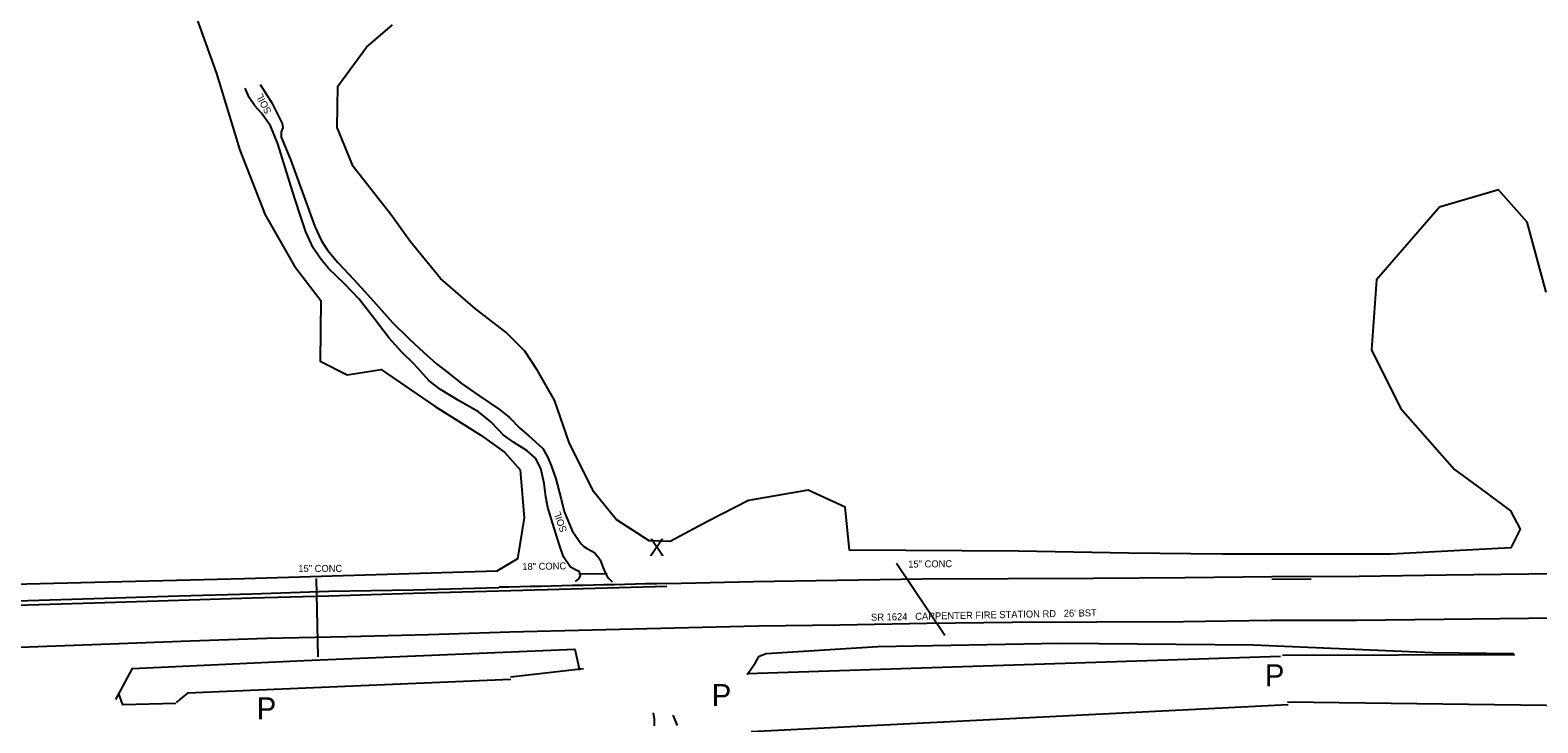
# Model space of a CAD drawing. Extents: x 2030130 to 2036320, y 723205 to 762423.
# Drawn here: x 2031448 to 2032310, y 754334 to 754729 of the extents above; entities that cross this region are included whole.
import ezdxf

# ---------------------------------------------------------------- set-up
doc = ezdxf.new("R2010")
doc.units = 0
for name, color, linetype in [('Draft_Station Labels Major', 7, 'Continuous'), ('Draft_Station Tics Major', 7, 'Continuous'), ('Draft_Station Tics Minor', 7, 'Continuous'), ('Old_Level_23', 7, 'Continuous'), ('Old_Level_26', 7, 'Continuous'), ('Prop Horizontal Alignment Ramp', 7, 'Continuous')]:
    doc.layers.add(name, color=color, linetype=linetype)

msp = doc.modelspace()

# ---------------------------------------------------------------- linework, layer by layer
at = {"layer": 'Draft_Station Labels Major'}
for p, q in [((2031574.67, 754404.91), (2031618.56, 754406.17)), ((2031618.56, 754406.17), (2031666.97, 754407.55)), ((2031666.97, 754407.55), (2031715.65, 754408.99)), ((2031440.17, 754400.79), (2031484.32, 754402.17)), ((2031484.32, 754402.17), (2031532.82, 754403.6)), ((2031532.82, 754403.6), (2031574.67, 754404.91))]:
    msp.add_line(p, q, dxfattribs=at)
for points in [[(2031759.54, 754414.3), (2031761.49, 754415.85), (2031762.43, 754417.62), (2031762.32, 754418.95), (2031761.64, 754419.94), (2031760.26, 754420.54), (2031756.68, 754422.5), (2031752.82, 754428.45), (2031750.48, 754435.12), (2031746.61, 754447.29), (2031743.86, 754456.61), (2031742.66, 754462.58), (2031741.63, 754470.31), (2031739.79, 754478.89), (2031736.7, 754484.84), (2031731.86, 754489.02), (2031724.12, 754493.98), (2031718.29, 754498.1), (2031715.5, 754500.97), (2031711.14, 754505.49), (2031704.06, 754511.16), (2031693.07, 754517.47), (2031682.47, 754524.06), (2031675.82, 754528.98), (2031670.87, 754534.39), (2031667.22, 754538.68), (2031660.32, 754545.31), (2031653.07, 754553.35), (2031644.42, 754564.48), (2031635.81, 754575.6), (2031627.55, 754584.4), (2031618.35, 754593.14), (2031613.5, 754599.08), (2031609.64, 754605.02), (2031605.42, 754614.1), (2031601.75, 754624.89), (2031597.69, 754637.24), (2031589.31, 754664.37), (2031585.17, 754674.73), (2031580.07, 754681.8), (2031576.18, 754685.99), (2031573, 754690.85), (2031570.76, 754696.19)], [(2031579.34, 754698.22), (2031585.94, 754687.84), (2031591.85, 754675.93), (2031592.16, 754673.51), (2031591.33, 754671.23), (2031591.26, 754668.23), (2031596.61, 754655.42), (2031604.96, 754632.37), (2031610.43, 754617.14), (2031614.3, 754608.87), (2031617.82, 754603.58), (2031623.64, 754596.56), (2031630.11, 754589.69), (2031636.98, 754582.31), (2031645.76, 754572.51), (2031654.93, 754562.3), (2031664.47, 754552.94), (2031672.62, 754545.38), (2031680.09, 754538.61), (2031686.55, 754533.64), (2031694.35, 754527.45), (2031704.39, 754520.66), (2031716.15, 754512.66), (2031721.8, 754507.97), (2031727.79, 754501.85), (2031732.82, 754497.58), (2031736.46, 754494.34), (2031740.87, 754490.2), (2031743.62, 754485.48), (2031745.71, 754480.56), (2031748.3, 754473.04), (2031751.41, 754461.25), (2031753.19, 754454.28), (2031757.62, 754443.26), (2031762.77, 754435.81), (2031764.35, 754434.31), (2031765.79, 754433.37), (2031767.65, 754432.39), (2031768.89, 754431.69), (2031770.85, 754430.24), (2031772, 754429.02), (2031773.01, 754427.84), (2031773.64, 754426.66), (2031775.49, 754422.07), (2031776.27, 754419.89), (2031776.85, 754418.62), (2031777.72, 754417.1), (2031778.63, 754415.97), (2031780.6, 754414.09)], [(2031811.89, 754413.13), (2031861.33, 754414.38), (2031909.16, 754415.12), (2031958.06, 754415.73), (2032007.08, 754416.04), (2032055.76, 754416.25), (2032108.13, 754416.62), (2032157.75, 754417.06), (2032207.7, 754417.33), (2032257.5, 754418.05), (2032304.72, 754418.6), (2032351.94, 754419.11), (2032398.25, 754419.75), (2032449.52, 754420.76), (2032467.91, 754421.36), (2032499.63, 754422.6), (2032537.02, 754423.46)], [(2032157.76, 754415.61), (2032180.27, 754415.79)], [(2031026.74, 754387.19), (2031087.38, 754389.72), (2031140.32, 754391.43), (2031191.98, 754393.68), (2031244.3, 754395.39), (2031296.79, 754397.49), (2031347.82, 754399.72), (2031392.09, 754401.58), (2031440.04, 754403.3), (2031484.2, 754404.5), (2031532.77, 754406.1), (2031574.56, 754407.31), (2031618.48, 754408.73), (2031666.93, 754409.56), (2031715.67, 754410.95)], [(2031715.65, 754408.99), (2031764.02, 754410.28), (2031811.79, 754411.53)], [(2031401.23, 754375.11), (2031446.88, 754377.01), (2031493.42, 754378.62), (2031539.16, 754380.32), (2031583.12, 754381.86), (2031629.01, 754382.93), (2031675.51, 754383.95), (2031722, 754385.62), (2031769.03, 754386.67), (2031816.14, 754387.79), (2031864.12, 754389), (2031910.83, 754389.54), (2031960.57, 754390.48), (2032009.47, 754390.99), (2032057.5, 754391.22), (2032107.26, 754391.52), (2032157.41, 754392.21), (2032206.33, 754392.27)], [(2032206.33, 754392.27), (2032256.13, 754392.71), (2032304.69, 754393.4), (2032351.64, 754393.89)], [(2031804.83, 754331.89), (2031804.79, 754335.59), (2031804.28, 754339.19)], [(2031815.3, 754337.97), (2031817.74, 754331.92)]]:
    msp.add_lwpolyline(points, dxfattribs=at)
msp.add_arc((2040522.98, 366896.92), 387614.11, 91.2877516, 91.3019787, dxfattribs=at)
at = {"layer": 'Draft_Station Tics Major'}
for p, q in [((2032162.74, 754371.48), (2031857.84, 754361.58)), ((2032296.83, 754372.45), (2032163.84, 754371.96)), ((2031764.07, 754364.44), (2031722.38, 754359.66)), ((2032166.83, 754345.57), (2032331.51, 754343.51)), ((2031860.04, 754328.57), (2032167.14, 754343.97))]:
    msp.add_line(p, q, dxfattribs=at)
for points in [[(2031533.5, 754762.53), (2031554.26, 754704.61), (2031567.65, 754660.73), (2031582.11, 754623.71), (2031598.79, 754594.53), (2031614.03, 754574.86), (2031613.61, 754540.18), (2031628.93, 754532.32), (2031648.53, 754535.37), (2031679.41, 754514.33), (2031705.49, 754497.82), (2031718.92, 754488.23), (2031727.97, 754478.03), (2031730.15, 754450.61), (2031726.37, 754427.33), (2031714.63, 754420.16), (2031570.23, 754415.89), (2031383.35, 754411.21)], [(2032314.64, 754579.61), (2032303.77, 754619.52), (2032287.39, 754638.03), (2032253.76, 754628.18), (2032217.77, 754586.67), (2032214.73, 754546.62), (2032231.45, 754513.25), (2032262.28, 754478.3), (2032280.7, 754464.76), (2032294.33, 754454.6), (2032299.77, 754444.17), (2032294.54, 754433.45), (2032225.97, 754429.92), (2032129.36, 754429.93), (2032075.81, 754430.55), (2032012.92, 754431.65), (2031916.31, 754432.23), (2031913.78, 754456.79), (2031892.72, 754466.49), (2031858.48, 754460.63), (2031835.54, 754448.78), (2031813.74, 754437.14), (2031801.73, 754437.59), (2031782.94, 754449.79), (2031769.83, 754465.67), (2031756.02, 754493.74), (2031747.59, 754517.86), (2031737.9, 754534.91), (2031730.55, 754545.89), (2031719.77, 754556.84), (2031702.49, 754570.01), (2031682.32, 754587.34), (2031665.15, 754608.33), (2031653.95, 754624.03), (2031632.34, 754651.45), (2031623.36, 754673.66), (2031623.7, 754697.29), (2031640.06, 754719.55), (2031654.99, 754732.27)], [(2031496.68, 754346.91), (2031506.26, 754364.58), (2031604.35, 754369.16), (2031759.2, 754375.63), (2031761.85, 754363.67)], [(2031857.78, 754361.11), (2031862.4, 754367.69), (2031864.59, 754371.61)], [(2031864.72, 754371.55), (2031868.6, 754373.08), (2031932.4, 754377.13), (2032036.8, 754379.1), (2032147.33, 754378.09), (2032249.7, 754373.75), (2032296.22, 754373.14)], [(2031722.67, 754358.27), (2031537.75, 754350.57), (2031531.14, 754345.07)], [(2031531.04, 754344.5), (2031500.74, 754343.83), (2031498.2, 754350.62)]]:
    msp.add_lwpolyline(points, dxfattribs=at)
at = {"layer": 'Draft_Station Tics Minor'}
for p, q in [((2031943.24, 754424.74), (2031970.83, 754383.64)), ((2031611.35, 754415.95), (2031612.17, 754371.32))]:
    msp.add_line(p, q, dxfattribs=at)
msp.add_lwpolyline([(2031761.51, 754418.58), (2031777.61, 754418.88)], dxfattribs=at)

# ---------------------------------------------------------------- texts
at = {"layer": 'Draft_Station Tics Major'}
msp.add_text('X', height=10, dxfattribs=at).set_placement((2031801.6, 754428.82))
at = {"layer": 'Old_Level_23'}
for s, rotation, p in [('SOIL', 117.22958, (2031585.86, 754682.76)), ('SOIL', 109.69681, (2031754.82, 754443.25)), ("SR 1624   CARPENTER FIRE STATION RD   26' BST", 1.16049, (2031928.63, 754391.85))]:
    msp.add_text(s, height=4, rotation=rotation, dxfattribs=at).set_placement(p)
at = {"layer": 'Old_Level_26'}
for s, rotation, p in [('15" CONC', 0.10649, (2031601.07, 754419.75)), ('18" CONC', 1.12252, (2031729.21, 754420.77)), ('15" CONC', 0.52894, (2031949.9, 754422.24))]:
    msp.add_text(s, height=4, rotation=rotation, dxfattribs=at).set_placement(p)
at = {"layer": 'Prop Horizontal Alignment Ramp'}
for p in [(2032153.86, 754354.47), (2031837.52, 754343.17), (2031577.29, 754335.56)]:
    msp.add_text('P', height=12.5, dxfattribs=at).set_placement(p)

doc.saveas('drawing.dxf')
